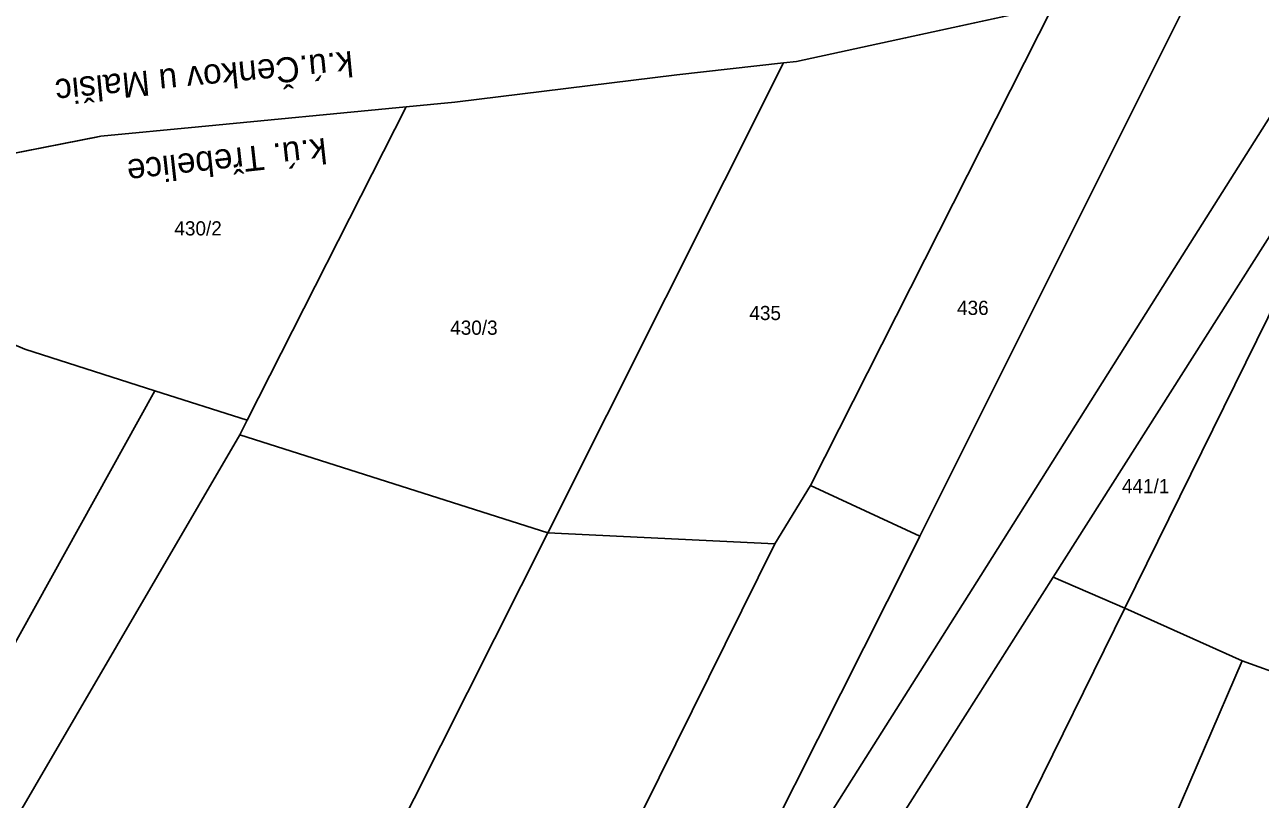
# Model space of a CAD drawing. Extents: x -746176 to -739709, y -1128407 to -1124482.
# Drawn here: x -743187.2 to -743038.9, y -1126959.6 to -1126866.7 of the extents above; entities that cross this region are included whole.
import ezdxf

# ---------------------------------------------------------------- set-up
doc = ezdxf.new("R2010")
doc.units = 0
for name, color, linetype in [('_Zabezpečovací zařízení_trasa', 7, 'Continuous'), ('Hranice parcel', 7, 'Continuous'), ('Parcelní čísla', 7, 'Continuous'), ('Vrstva 53', 7, 'Continuous'), ('Vrstva 55', 7, 'Continuous')]:
    doc.layers.add(name, color=color, linetype=linetype)

msp = doc.modelspace()

# ---------------------------------------------------------------- linework, layer by layer
at = {"layer": '_Zabezpečovací zařízení_trasa'}
msp.add_lwpolyline([(-743018.82, -1126847.74), (-743049.28, -1126895.95), (-743072.49, -1126932.75), (-743098.65, -1126974.15), (-743125.94, -1127017.38), (-743152.6, -1127059.61), (-743175.02, -1127095.12), (-743199.16, -1127133.35), (-743215.97, -1127159.94), (-743232.82, -1127186.51), (-743247.46, -1127209.81), (-743254.52, -1127221.64), (-743261.3, -1127233.69), (-743264.16, -1127239.2), (-743264.86, -1127241.11), (-743267.34, -1127245.82), (-743268.29, -1127247.16), (-743271.71, -1127253.75), (-743281.12, -1127274.2), (-743291.92, -1127301.42), (-743296.72, -1127315.22), (-743301.12, -1127329.13), (-743306.79, -1127349.51)], dxfattribs=at)
at = {"layer": 'Hranice parcel'}
for p, q in [((-743092.91, -1126921.98), (-743063.79, -1126864.46)), ((-743124.42, -1126927.65), (-743096.16, -1126871.29)), ((-743160.51, -1126914.13), (-743141.43, -1126876.56)), ((-743160.51, -1126914.13), (-743171.59, -1126910.6)), ((-743161.41, -1126915.91), (-743160.51, -1126914.13)), ((-743161.41, -1126915.91), (-743124.42, -1126927.65)), ((-743097.21, -1126928.95), (-743092.91, -1126921.98)), ((-743092.91, -1126921.98), (-743079.79, -1126928.05)), ((-743097.21, -1126928.95), (-743124.42, -1126927.65)), ((-743079.79, -1126928.05), (-743080.97, -1126930.41)), ((-743082.27, -1126962.07), (-743063.8, -1126932.98)), ((-743063.8, -1126932.98), (-743055.18, -1126936.67)), ((-743055.18, -1126936.67), (-743041.11, -1126943.01)), ((-743030.98, -1126946.66), (-743041.11, -1126943.01))]:
    msp.add_line(p, q, dxfattribs=at)
for points in [[(-743045.12, -1126860.39), (-743048.51, -1126865.51), (-743079.79, -1126928.05)], [(-743096.16, -1126871.29), (-743094.61, -1126871.12), (-743081.5, -1126868.29), (-743066.4, -1126865.02), (-743063.79, -1126864.46)], [(-743096.16, -1126871.29), (-743094.61, -1126871.12), (-743081.5, -1126868.29), (-743066.4, -1126865.02), (-743063.79, -1126864.46)], [(-743063.8, -1126932.98), (-743032.8, -1126884.17), (-743022.51, -1126867.46)], [(-743055.18, -1126936.67), (-743038.05, -1126901.87), (-743022.51, -1126867.46)], [(-743141.43, -1126876.56), (-743135.6, -1126876), (-743108.94, -1126872.71), (-743096.16, -1126871.29)], [(-743141.43, -1126876.56), (-743135.6, -1126876), (-743108.94, -1126872.71), (-743096.16, -1126871.29)], [(-743209.04, -1126886.14), (-743178.59, -1126880.18), (-743178.08, -1126880.08), (-743166.37, -1126878.96), (-743141.43, -1126876.56)], [(-743209.04, -1126886.14), (-743178.59, -1126880.18), (-743178.08, -1126880.08), (-743166.37, -1126878.96), (-743141.43, -1126876.56)], [(-743171.59, -1126910.6), (-743187.18, -1126905.63), (-743191.74, -1126903.68), (-743193, -1126906.14)], [(-743263.8, -1127077.63), (-743246.71, -1127046.03), (-743171.59, -1126910.6)], [(-743250.75, -1127079.85), (-743230.59, -1127039.01), (-743190.96, -1126966.49), (-743161.41, -1126915.91)], [(-743206.78, -1127087.5), (-743159.7, -1126997.73), (-743124.42, -1126927.65)], [(-743178.51, -1127091.81), (-743158.66, -1127053.1), (-743097.21, -1126928.95)], [(-743080.97, -1126930.41), (-743108.67, -1126985.4), (-743124.8, -1127012.28), (-743175.35, -1127091.16), (-743178.51, -1127091.81)], [(-743119.42, -1127081.96), (-743118.49, -1127078.74), (-743112.93, -1127064.74), (-743067.57, -1126961.77), (-743055.18, -1126936.67)], [(-743041.11, -1126943.01), (-743050.16, -1126963.96), (-743083.16, -1127038.56), (-743100.51, -1127085.04)]]:
    msp.add_lwpolyline(points, dxfattribs=at)
at = {"layer": 'Vrstva 53'}
msp.add_lwpolyline([(-743032.8, -1126884.17), (-743063.8, -1126932.98), (-743082.27, -1126962.07), (-743093.1, -1126978.92), (-743136.47, -1127047.12), (-743147.78, -1127068.8), (-743159.64, -1127094.74), (-743160.17, -1127095.91), (-743166.78, -1127095.57), (-743176.42, -1127093.47), (-743180.17, -1127093.19), (-743180.08, -1127092.14), (-743178.51, -1127091.81), (-743175.35, -1127091.16), (-743150.08, -1127051.72), (-743124.8, -1127012.28), (-743108.67, -1126985.4), (-743080.97, -1126930.41), (-743079.79, -1126928.05), (-743048.51, -1126865.51), (-743045.12, -1126860.39), (-743029.24, -1126857.99)], dxfattribs=at)
at = {"layer": 'Vrstva 55'}
msp.add_lwpolyline([(-743029.24, -1126857.99), (-743045.12, -1126860.39), (-743063.79, -1126864.46), (-743081.5, -1126868.29), (-743094.61, -1126871.12), (-743096.16, -1126871.29), (-743108.94, -1126872.71), (-743135.6, -1126876), (-743141.43, -1126876.56), (-743166.37, -1126878.96), (-743178.08, -1126880.08), (-743209.04, -1126886.14), (-743225.02, -1126889.27), (-743239.29, -1126892.07)], dxfattribs=at)

# ---------------------------------------------------------------- texts
at = {"layer": 'Parcelní čísla'}
for s, p in [('430/2', (-743169.25, -1126891.98)), ('435', (-743100.25, -1126902.13)), ('436', (-743075.33, -1126901.51)), ('430/3', (-743136.15, -1126903.89)), ('441/1', (-743055.54, -1126922.89))]:
    msp.add_text(s, height=1.7, dxfattribs=at).set_placement(p)
at = {"layer": 'Vrstva 55'}
for s, rotation, p in [('k.ú.Čenkov u Malšic', 185.4967, (-743147.93, -1126869.84)), ('k.ú. Třebelice', 186.3402, (-743151.13, -1126880.27))]:
    msp.add_text(s, height=3, rotation=rotation, dxfattribs=at).set_placement(p)

doc.saveas('drawing.dxf')
